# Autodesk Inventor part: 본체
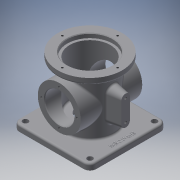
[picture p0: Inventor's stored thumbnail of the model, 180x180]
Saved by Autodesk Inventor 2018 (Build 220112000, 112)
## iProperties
Created: 2017-08
Part Number: 본체
Material: 알루미늄 6061
Document SubType Name: Modeling
Designer: mduedu
Density: 2.71 g/cm^3
Mass: 951.115 g
Surface Area: 966.539 cm^2
Volume: 350.965 cm^3
Appearance: 기본값
Author: mduedu
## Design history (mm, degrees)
sketch "스케치1"
  geometry: L1 (-62.5, -62.5)-(62.5, -62.5); L2 (62.5, -62.5)-(62.5, 62.5); L3 (62.5, 62.5)-(-62.5, 62.5); L4 (-62.5, 62.5)-(-62.5, -62.5); L5 (-62.5, -62.5)-(62.5, 62.5); L6 (62.5, -62.5)-(-62.5, 62.5); 1 further point
  constraints: 12 end point, 2 midpoint, 2 parallel, 1 horizontal, 1 perpendicular
  dimensions: "d232" = 125 distance of L3.end L2.end; "d233" = 125 distance of L2.end L1.end
extrude "돌출1" new body sketch "스케치1" distance "d5" = 10; taper "d6" = 0 deg
sketch "스케치2"
  geometry: C1 r 38 at (0, 0); 1 further point
  constraints: 1 centre point, 1 coincident
  dimensions: "d111" = 76 diameter of C1
extrude "돌출2" join sketch "스케치2" distance "d12" = 88; taper "d13" = 0 deg
sketch "스케치3"
  geometry: C1 r 52.5 at (0, 0); 1 further point
  constraints: 1 centre point, 1 coincident
  dimensions: "d114" = 105 diameter of C1
extrude "돌출3" join sketch "스케치3" distance "d19" = 10; taper "d20" = 0 deg
sketch "스케치4"
  geometry: C1 r 33 at (0, 0); 1 further point
  constraints: 1 centre point, 1 coincident
  dimensions: "d115" = 66 diameter of C1
extrude "돌출4" cut sketch "스케치4" distance "d26" = 86; taper "d27" = 0 deg
sketch "스케치5"
  geometry: C1 r 37 at (0, 0); 1 further point
  constraints: 1 centre point, 1 coincident
  dimensions: "d116" = 74 diameter of C1
extrude "돌출5" cut sketch "스케치5" distance "d29" = 7; taper "d30" = 0 deg
node "작업 평면1"
sketch "스케치18"
  geometry: L1 (-62.5, 0)-(62.5, 0) reference; C1 r 35 at (0, 54); 1 further point
  constraints: 1 centre point, 1 vertical alignment
  dimensions: "d118" = 70 diameter of C1; "d234" = 54 distance from line of C1.centre L1
extrude "돌출9" join sketch "스케치18" stored distance "d120" = 10; taper "d121" = 0 deg
hole "구멍8" diameter "d124" = 48; stored, may be unused: countersink angle "d128" = 90 deg, drill point angle "d130" = 118 deg; dims "d122" = 10, "d123" = 10, "d125" = 6, "d126" = 4, "d127" = 2, "d129" = 8
sketch "스케치9"
  geometry: C1 r 33 at (0, 0); 1 further point
  constraints: 1 centre point, 1 coincident
  dimensions: "d131" = 66 diameter of C1
extrude "돌출8" cut sketch "스케치9" distance "d43" = 16; taper "d44" = 0 deg
node "작업 평면2"
fillet "모깎기9" dims "d137" = 3
fillet "모깎기10" dims "d138" = 3
chamfer "모따기2" distance "d139" = 1; stored, may be unused: second distance "d140" = 2, angle "d141" = 45 deg
fillet "모깎기11" dims "d142" = 3
fillet "모깎기12" dims "d143" = 3
fillet "모깎기13" dims "d144" = 3
node "작업 평면3"
sketch "스케치20"
  geometry: L1 (108, -52.5)-(108, 52.5) reference; L2 (37, 7)-(71, 7); L3 (37, -7)-(71, -7); L4 (0, -33)-(0, 33) reference; A1 r 7 centre (37, 0) between (37, 7) and (37, -7); A2 r 7 centre (71, 0) between (71, 7) and (71, -7); 1 further point
  constraints: 4 end point, 4 point on circle, 3 tangent, 2 centre point, 2 horizontal alignment, 1 parallel, 1 perpendicular
  dimensions: "d203" = 14 diameter of A1; "d206" = 30 distance edge to line of A2 L1; "d207" = 48 dimension on A2 A1 (derived); "d236" = 30 distance edge to line of A1 L4
extrude "돌출10" join sketch "스케치20" stored distance "d152" = 10; taper "d153" = 10 deg
sketch "스케치21"
  geometry: C1 r 7 at (0, 71) reference; C2 r 7 at (0, 37) reference; 3 further points
  constraints: 2 coincident
hole "구멍12" sketch "스케치21" at (0, 71), (0, 37) diameter "d219" = 4.134; stored, may be unused: countersink angle "d223" = 90 deg, drill point angle "d225" = 118 deg; dims "d220" = 6, "d221" = 4, "d222" = 2, "d224" = 8
fillet "모깎기18" dims "d229" = 3
sketch "스케치23"
  geometry: C1 r 20 at (0, 0); 1 further point
  constraints: 1 centre point, 1 coincident
  dimensions: "d168" = 40 diameter of C1
extrude "돌출12" cut sketch "스케치23" extent not by distance; stored distance "d169" = 148.25; taper "d170" = 0 deg
sketch "스케치28"
  geometry: L1 (62.5, -62.5)-(62.5, 62.5) reference; 2 further points
  constraints: 1 horizontal alignment, 1 other
  dimensions: "d238" = 10 distance from line of point (52.5, 0) L1
feature "엠보싱4" sketch "스케치28" dims "d239" = 0.5, "d240" = 0
sketch "스케치25" dims "d178" = 58
  geometry: C1 r 35 at (0, 0) reference; 3 further points
  constraints: 2 vertical alignment, 1 coincident, 2 other
hole "구멍10" sketch "스케치25" at (0, 29) diameter "d179" = 3.242; stored, may be unused: countersink angle "d183" = 90 deg, drill point angle "d185" = 118 deg; dims "d180" = 4, "d181" = 4, "d182" = 2, "d184" = 6
sketch "스케치26" dims "d189" = 90
  geometry: 3 further points
  constraints: 2 vertical alignment, 1 coincident, 2 other
hole "구멍11" sketch "스케치26" at (0, 45) diameter "d190" = 3.242; stored, may be unused: countersink angle "d194" = 90 deg, drill point angle "d196" = 118 deg; dims "d191" = 4, "d192" = 4, "d193" = 2, "d195" = 6
chamfer "모따기4" distance "d200" = 1; stored, may be unused: second distance "d201" = 2, angle "d202" = 45 deg
fillet "모깎기19" dims "d241" = 10
sketch "스케치29"
  geometry: A1 r 10 centre (-52.5, 52.5) between (-52.5, 62.5) and (-62.5, 52.5) reference; A2 r 10 centre (52.5, 52.5) between (62.5, 52.5) and (52.5, 62.5) reference; A3 r 10 centre (52.5, -52.5) between (52.5, -62.5) and (62.5, -52.5) reference; A4 r 10 centre (-52.5, -52.5) between (-62.5, -52.5) and (-52.5, -62.5) reference; 5 further points
  constraints: 4 coincident
hole "구멍13" sketch "스케치29" at (-52.5, 52.5), (52.5, 52.5), (52.5, -52.5), (-52.5, -52.5) diameter "d242" = 9; stored, may be unused: countersink angle "d246" = 90 deg, drill point angle "d248" = 118 deg; dims "d243" = 6, "d244" = 4, "d245" = 2, "d247" = 8
fillet "모깎기20" dims "d249" = 3
node "솔리드1"
mirror "대칭2"
pattern_circular "원형 패턴1" dims angle "d187" = 360 deg
mirror "대칭3"
pattern_circular "원형 패턴2" dims angle "d198" = 360 deg
other parameters: "d147" = 58
